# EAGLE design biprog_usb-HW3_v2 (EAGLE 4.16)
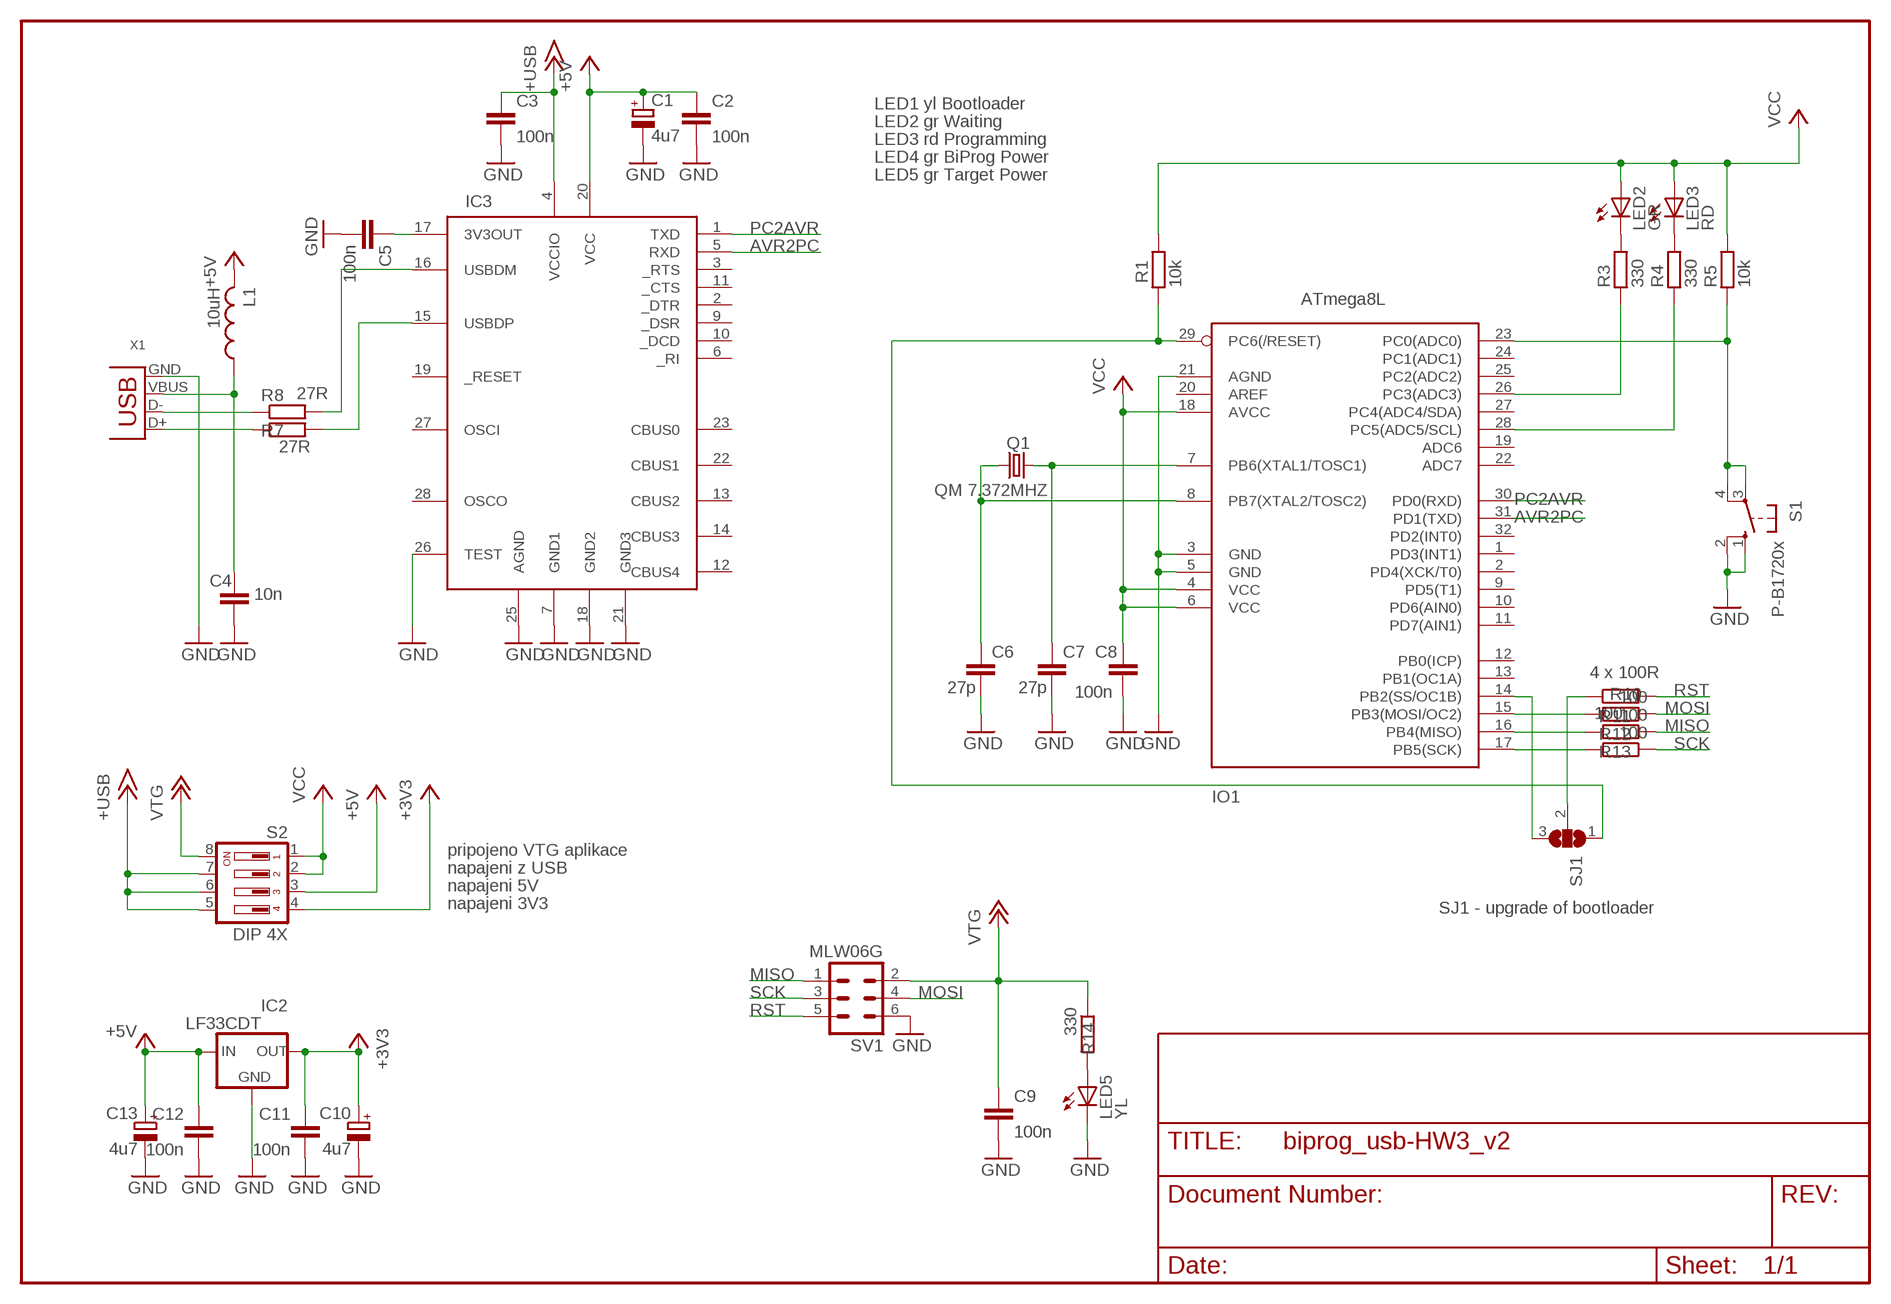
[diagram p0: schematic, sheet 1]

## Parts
C1  4u7  CPOL-EUSMCA  [SMC_A]
C2  100n  C-EUC1206  [C1206]
C3  100n  C-EUC1206  [C1206]
C4  10n  C-EUC1206  [C1206]
C5  100n  C-EUC1206  [C1206]
C6  27p  C-EUC1206  [C1206]
C7  27p  C-EUC1206  [C1206]
C8  100n  C-EUC1206  [C1206]
C9  100n  C-EUC1206  [C1206]
C10  4u7  CPOL-EUSMCA  [SMC_A]
C11  100n  C-EUC1206  [C1206]
C12  100n  C-EUC1206  [C1206]
C13  4u7  CPOL-EUSMCA  [SMC_A]
IC2  LF33CDT  LP2950CDTX-3.3  [DPACK]
IC3  FT232RL  [SSOP28DB]
IO1  ATmega8L  MEGA8-AI  [TQFP32-08]
L1  10uH  L-US0207/10  [0207/10]
LED2  GR  LED3MM  [LED3MM]
LED3  RD  LED3MM  [LED3MM]
LED5  YL  LED3MM  [LED3MM]
Q1  QM 7.372MHZ  CRYTALHC49S  [HC49/S]
R1  10k  R-EU_R1206  [R1206]
R3  330  R-EU_R1206  [R1206]
R4  330  R-EU_R1206  [R1206]
R5  10k  R-EU_R1206  [R1206]
R7  27R  R-EU_R1206  [R1206]
R8  27R  R-EU_R1206  [R1206]
R10  100  R-EU_R1206  [R1206]
R11  100  R-EU_R1206  [R1206]
R12  100  R-EU_R1206  [R1206]
R13  100  R-EU_R1206  [R1206]
R14  330  R-EU_R1206  [R1206]
S1  P-B1720x  10-XX  [B3F-10XX]
S2  DIP 4X  DS04  [DS-04]
SJ1  SJ2W  [SJ_2]
SV1  MLW06G  ML6  [ML6]
X1  USB-MINI B F SMD  USB-MB-S  [USB-MB-S]

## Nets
+3V3: C10.+ C11.1 IC2.3(OUT) S2.4
+5V: C1.+ C2.1 C12.1 C13.+ IC2.1(IN) IC3.20(VCC) L1.2 S2.3
+12V: C9.1 R14.1 S2.8 SV1.2 ; supply symbol labelled VTG
+15V: C3.1 IC3.4(VCCIO) S2.5 S2.6 S2.7 ; supply symbol labelled +USB
AVR2PC: IC3.5(RXD) IO1.31(PD1(TXD))
GND: C1.- C2.2 C3.2 C4.2 C5.2 C6.2 C7.2 C8.1 C9.2 C10.- C11.2 C12.2 C13.- IC2.4(GND) IC3.7(GND1) IC3.18(GND2) IC3.21(GND3) IC3.25(AGND) IC3.26(TEST) IO1.3(GND) IO1.5(GND) IO1.21(AGND) LED5.K(C) S1.1(S) S1.2(S1) SV1.6 X1.GND
MISO: R12.1 SV1.1
MOSI: R11.1 SV1.4
N$1: C7.1 IO1.7(PB6(XTAL1/TOSC1)) Q1.1
N$2: LED2.K(C) R3.2
N$3: LED3.K(C) R4.2
N$4: IO1.23(PC0(ADC0)) R5.1 S1.3(P) S1.4(P1)
N$6: LED5.A R14.2
N$8: C4.1 L1.1 X1.VBUS
N$9: IC3.15(USBDP) R8.2
N$11: C6.1 IO1.8(PB7(XTAL2/TOSC2)) Q1.2
N$12: R7.1 X1.D-
N$13: R8.1 X1.D+
N$16: IO1.17(PB5(SCK)) R13.2
N$17: IO1.16(PB4(MISO)) R12.2
N$18: IO1.15(PB3(MOSI/OC2)) R11.2
N$19: R10.1 SJ1.2
N$20: IO1.14(PB2(SS/OC1B)) SJ1.3
N$22: IC3.16(USBDM) R7.2
N$23: C5.1 IC3.17(3V3OUT)
N$24: IO1.29(PC6(/RESET)) R1.1 SJ1.1
N$37: IO1.26(PC3(ADC3)) R3.1
N$40: IO1.28(PC5(ADC5/SCL)) R4.1
PC2AVR: IC3.1(TXD) IO1.30(PD0(RXD))
RST: R10.2 SV1.5
SCK: R13.1 SV1.3
VCC: C8.2 IO1.4(VCC) IO1.6(VCC) IO1.18(AVCC) LED2.A LED3.A R1.2 R5.2 S2.1 S2.2
Unconnected: IC3.2(_DTR) IC3.3(_RTS) IC3.6(_RI) IC3.9(_DSR) IC3.10(_DCD) IC3.11(_CTS) IC3.12(CBUS4) IC3.13(CBUS2) IC3.14(CBUS3) IC3.19(_RESET) IC3.22(CBUS1) IC3.23(CBUS0) IC3.27(OSCI) IC3.28(OSCO) IO1.1(PD3(INT1)) IO1.2(PD4(XCK/T0)) IO1.9(PD5(T1)) IO1.10(PD6(AIN0)) IO1.11(PD7(AIN1)) IO1.12(PB0(ICP)) IO1.13(PB1(OC1A)) IO1.19(ADC6) IO1.20(AREF) IO1.22(ADC7) IO1.24(PC1(ADC1)) IO1.25(PC2(ADC2)) IO1.27(PC4(ADC4/SDA)) IO1.32(PD2(INT0))

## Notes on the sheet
- LED1 yl Bootloader
- LED2 gr Waiting
- LED3 rd Programming
- LED4 gr BiProg Power
- LED5 gr Target Power
- 4 x 100R
- pripojeno VTG aplikace
- napajeni z USB
- napajeni 5V
- napajeni 3V3 | SJ1 - upgrade of bootloader

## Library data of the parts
C1 C10 C13 = rcl:CPOL-EU: POLARIZED CAPACITOR, European symbol
C2-C9 C11 C12 = rcl:C-EU: CAPACITOR, European symbol
IC2 = v-reg:LP2950?*: Source: http://cache.national.com/ds/LP/LP2950.pdf
IC3 = ftdichip:FT232RL: USB UART 4th Generation USB UART (USB <-> Serial) Controller
IO1 = avr:MEGA8: MICROCONTROLLER 8 Kbytes FLASH 1 kbytes SRAM 512 bytes EEPROM USART 6-channel 10 bit ADC 2-channel 8 bit ADC
L1 = rcl:L-US: INDUCTOR, American symbol
LED2 LED3 LED5 = led:LED: LED
Q1 = crystal:CRYTAL: CRYSTAL
R1 R3-R5 R7 R8 R10-R14 = rcl:R-EU_: RESISTOR, European symbol
S1 = switch-omron:10-XX: OMRON SWITCH
S2 = switch-dil:DS04: DIL/CODE SWITCH
SJ1 = jumper:SJ2W: SMD solder JUMPER
SV1 = con-harting-ml:ML6: HARTING
X1 = con-usb-3:USB: USB Connectors

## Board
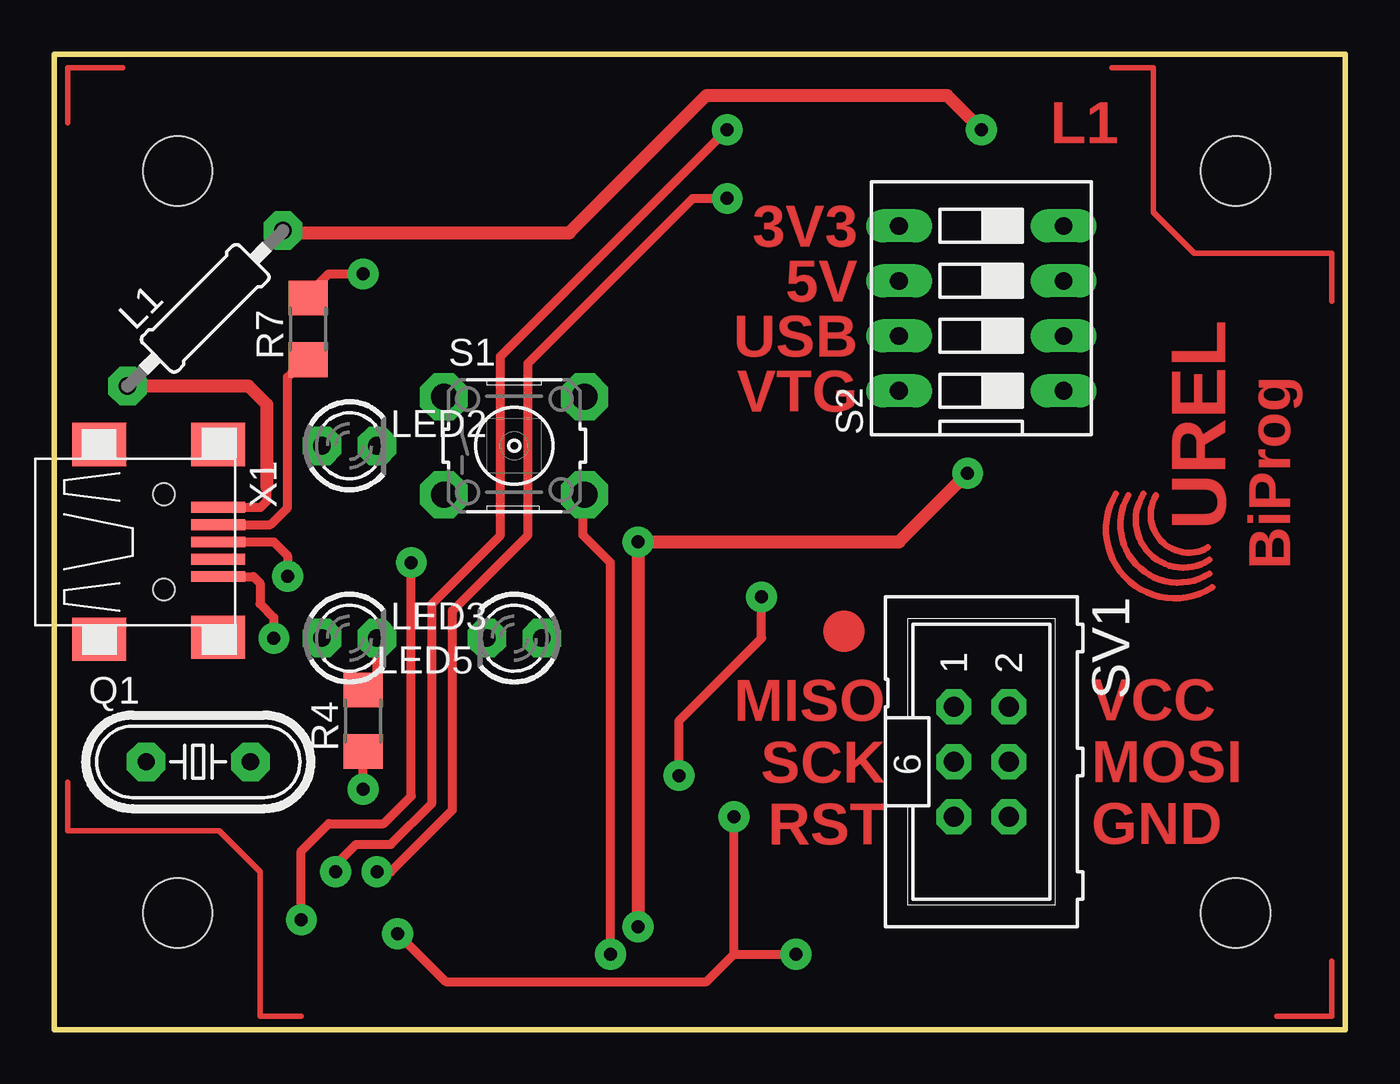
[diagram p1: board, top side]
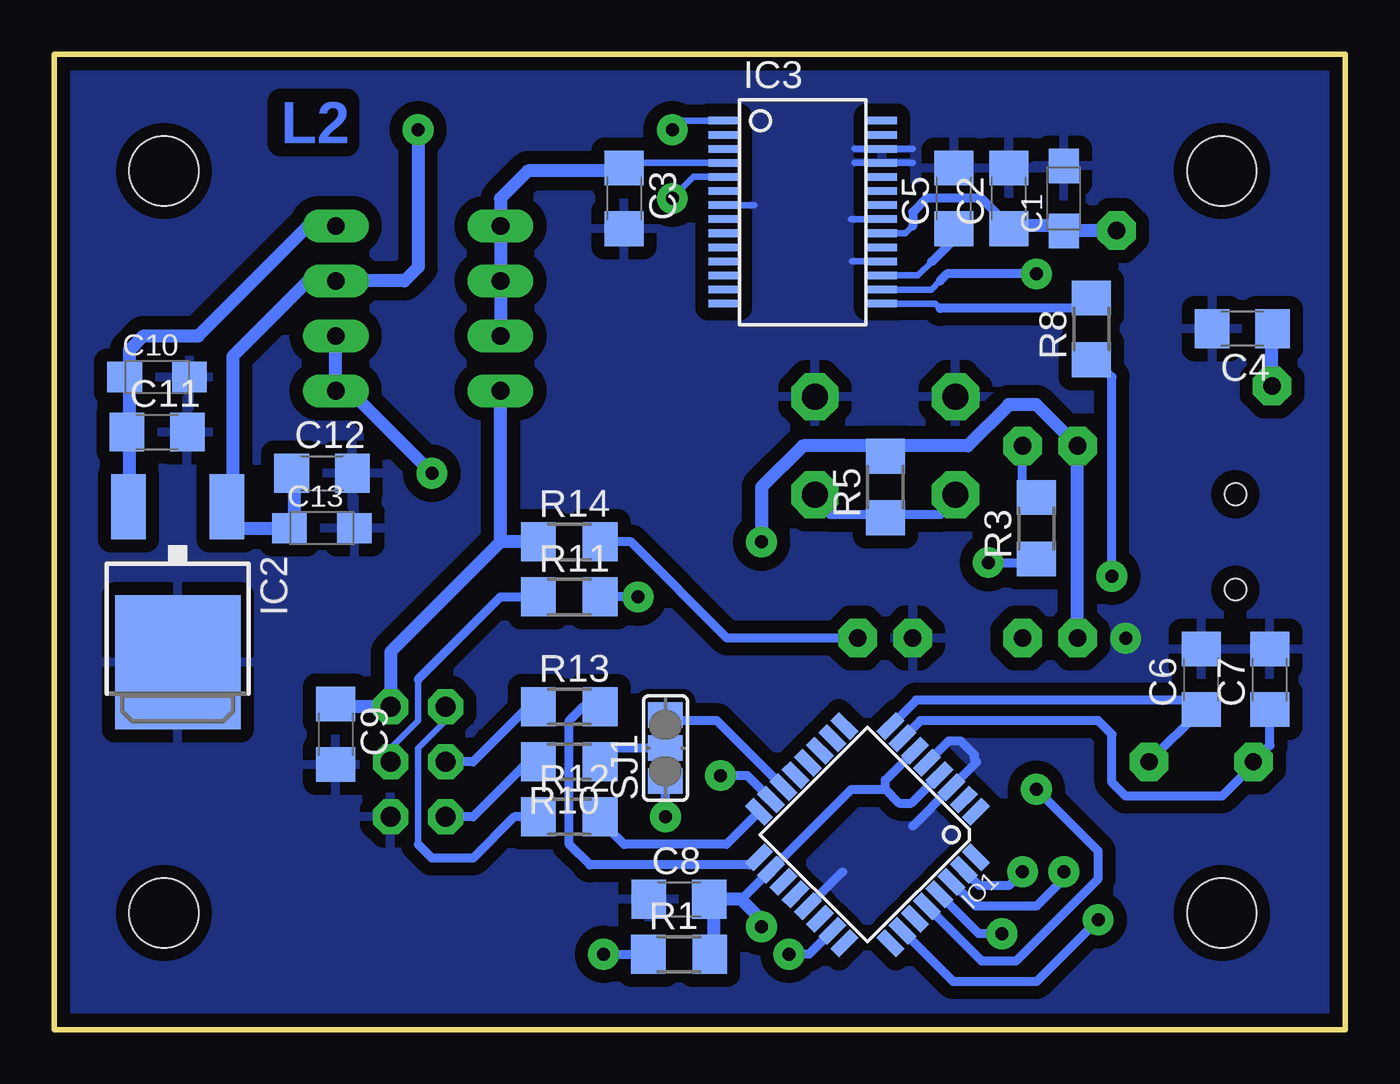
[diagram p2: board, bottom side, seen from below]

Size 59.69 x 45.09 mm. Coordinates in mm from the lower left corner, seen from the top.
Outline: 0,45.09 0,0 59.69,0 59.69,45.09 0,45.09
Copper layers (1*16): Top 0.035mm / dielectric 1.5mm / Bottom 0.035mm
Design rules "default": minimum track width 10mil, minimum drill 0.6mm, track to track 8mil, track to pad 8mil, pad to pad 8mil, via to via 8mil, smd to smd 8mil, copper to edge 1mil, drill to drill 8mil, minimum pad ring 14mil, minimum via ring 8mil, stop-mask expansion 4mil, vias tented up to drill 0.6mm, thermal gap 24mil
Holes 3.2 mm at 5.71,39.69 54.61,5.4 5.71,5.4 54.61,39.69

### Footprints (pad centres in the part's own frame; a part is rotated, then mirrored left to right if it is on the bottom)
SMC_A = smd 1.6 x 1.4: + -1.5,0; - 1.5,0
C1206 = smd 1.6 x 1.8: 1 -1.4,0; 2 1.4,0
DPACK = smd 1.6 x 3: 1 -2.28,-4.8; 3 2.28,-4.8 | smd 5.8 x 6.2: 4 0,2.38
SSOP28DB = smd 0.348 x 1.397: 1 -4.225,-3.656; 2 -3.575,-3.656; 3 -2.925,-3.656; 4 -2.275,-3.656; 5 -1.625,-3.656; 6 -0.975,-3.656; 7 -0.325,-3.656; 8 0.325,-3.656; 9 0.975,-3.656; 10 1.625,-3.656; 11 2.275,-3.656; 12 2.925,-3.656; 13 3.575,-3.656; 14 4.225,-3.656; 15 4.225,3.656; 16 3.575,3.656; 17 2.925,3.656; 18 2.275,3.656; 19 1.625,3.656; 20 0.975,3.656; 21 0.325,3.656; 22 -0.325,3.656; 23 -0.975,3.656; 24 -1.625,3.656; 25 -2.275,3.656; 26 -2.925,3.656; 27 -3.575,3.656; 28 -4.225,3.656
TQFP32-08 = smd 1.27 x 0.559: 1 -4.293,2.8; 2 -4.293,2; 3 -4.293,1.2; 4 -4.293,0.4; 5 -4.293,-0.4; 6 -4.293,-1.2; 7 -4.293,-2; 8 -4.293,-2.8; 17 4.293,-2.8; 18 4.293,-2; 19 4.293,-1.2; 20 4.293,-0.4; 21 4.293,0.4; 22 4.293,1.2; 23 4.293,2; 24 4.293,2.8 | smd 0.559 x 1.27: 9 -2.8,-4.293; 10 -2,-4.293; 11 -1.2,-4.293; 12 -0.4,-4.293; 13 0.4,-4.293; 14 1.2,-4.293; 15 2,-4.293; 16 2.8,-4.293; 25 2.8,4.293; 26 2,4.293; 27 1.2,4.293; 28 0.4,4.293; 29 -0.4,4.293; 30 -1.2,4.293; 31 -2,4.293; 32 -2.8,4.293
0207/10 = drill 0.813 pad 1.778 octagon: 1 -5.08,0; 2 5.08,0
LED3MM = drill 0.813 pad 1.778 octagon: A -1.27,0; K 1.27,0
HC49/S = drill 0.8 pad 1.778 octagon: 1 -2.413,0; 2 2.413,0
R1206 = smd 1.6 x 1.803: 1 -1.422,0; 2 1.422,0
B3F-10XX = drill 1.2 pad 2.184 octagon: 1 -3.251,2.261; 2 3.251,2.261; 3 -3.251,-2.261; 4 3.251,-2.261
DS-04 = drill 0.813 long: 1 -3.81,-3.81; 2 -1.27,-3.81; 3 1.27,-3.81; 4 3.81,-3.81; 5 3.81,3.81; 6 1.27,3.81; 7 -1.27,3.81; 8 -3.81,3.81
SJ_2 = smd 1.168 x 1.6: 1 -1.524,0; 2 0,0; 3 1.524,0
ML6 = drill 0.914 octagon: 1 -2.54,-1.27; 2 -2.54,1.27; 3 0,-1.27; 4 0,1.27; 5 2.54,-1.27; 6 2.54,1.27
USB-MB-S = smd 2.5 x 0.5: D+ 2.5,0; D- 2.5,0.8; GND 2.5,-1.6; ID 2.5,-0.8; VBUS 2.5,1.6 | smd 2.5 x 2: P$1 -3,-4.5; P$2 -3,4.5; P$3 2.5,-4.4; P$4 2.5,4.5 | hole 1: 0,2.2; 0,-2.2

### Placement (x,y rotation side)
C1  13.02,38.42 90 bottom
C2  15.56,38.42 90 bottom
C3  33.34,38.42 270 bottom
C4  4.76,32.38 180 bottom
C5  18.1,38.42 90 bottom
C6  6.67,16.19 90 bottom
C7  3.49,16.19 90 bottom
C8  30.8,6.03 0 bottom
C9  46.67,13.65 270 bottom
C10  54.93,30.16 0 bottom
C11  54.93,27.62 0 bottom
C12  47.31,25.72 0 bottom
C13  47.31,23.18 0 bottom
IC2  53.98,19.37 180 bottom
IC3  25.08,37.78 270 bottom
IO1  22.09,9.02 225 bottom
L1  6.99,33.34 45 top
LED2  13.65,26.99 0 top
LED3  13.65,18.1 0 top
LED5  21.27,18.1 180 top
Q1  6.67,12.38 0 top
R1  30.8,3.49 0 bottom
R3  14.29,23.18 90 bottom
R4  14.29,14.29 90 top
R5  21.27,25.08 90 bottom
R7  11.75,32.38 90 top
R8  11.75,32.38 90 bottom
R10  35.88,12.38 180 bottom
R11  35.88,20 0 bottom
R12  35.88,9.84 0 bottom
R13  35.88,14.92 0 bottom
R14  35.88,22.54 0 bottom
S1  21.27,26.99 0 top
S2  42.86,33.34 90 top
SJ1  31.43,13.02 90 bottom
SV1  42.86,12.38 270 top
X1  5.08,22.54 0 top

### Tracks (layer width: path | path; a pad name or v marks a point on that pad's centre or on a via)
+3V3
  Bottom 0.406: IC2.3 56.26,23.87 56.2,24.45 | 56.2,27.62 C11.1 | 56.2,30.16 C10.+
  Bottom 0.61: 56.2,24.45 56.2,27.62 56.2,30.16 56.2,31.43 55.56,32.07 53.02,32.07 47.94,37.15 S2.4
+5V  (via drill 0.6 pad 1.42)
  Top 0.406: L1.2 10.48,36.83
  Top 0.61: 10.48,36.83 23.81,36.83 30.16,43.18 41.27,43.18 v42.86,41.59
  Bottom 0.305: IC3.20 20.34,36.81 20,37.15
  Bottom 0.406: 20,37.15 20,37.78 19.37,38.42 16.83,38.42 15.56,37.15 C2.1 | 12.8,36.93 13.02,37.15 | 51.44,24.77 51.7,24.39 IC2.1 | 48.58,25.72 C12.1 | 51.7,23.23 51.75,23.18 | 48.58,23.18 C13.+
  Bottom 0.61: C1.+ 13.02,37.15 15.56,37.15 | L1.2 12.8,36.93 | v42.86,41.59 42.86,35.24 43.5,34.61 S2.3 47.94,34.61 51.44,31.11 51.44,24.77 | 48.58,25.72 48.58,23.18 51.75,23.18 | IC2.1 51.7,23.23
+12V
  Bottom 0.406: 46.67,14.92 C9.1 | R14.1 37.15,22.54
  Bottom 0.61: 46.67,14.92 SV1.2 44.13,17.46 39.05,22.54 | 39.05,22.54 S2.8 | R14.1 39.05,22.54
+15V
  Bottom 0.305: IC3.4 32.97,40.06 33.34,39.69
  Bottom 0.406: 33.34,39.69 C3.1
  Bottom 0.61: S2.7 S2.6 S2.5 39.05,38.42 37.78,39.69 33.34,39.69
AVR2PC  (via drill 0.6 pad 1.42)
  Top 0.406: v31.11,38.42 29.53,38.42 21.91,30.8 21.91,22.86 18.41,19.37 18.41,10.16 15.56,7.3 v14.92,7.3
  Bottom 0.305: IC3.5 30.12,39.41 v31.11,38.42
  Bottom 0.406: IO1.31 16.91,6.67 15.56,6.67 v14.92,7.3
GND  (via drill 0.6 pad 1.42)
  Top 0.406: X1.GND 9.22,20.94 9.53,20.64 9.53,19.68 10.16,19.05 v10.16,18.1
  Bottom 0.305: 21.27,40.71 IC3.26 | 20,40.71 21.27,40.71 | 21.27,40.06 IC3.25 | 20,40.06 21.27,40.06 | 21.27,40.71 22.7,40.71 | 21.27,40.06 22.7,40.06 | IC3.21 22.86,37.46 | 21.27,35.51 IC3.18 22.81,35.51 | 27.3,38.11 IC3.7
  Bottom 0.406: IO1.21 23.25,7.3 | 20,9.41 IO1.3 17.04,12.38 17.14,12.49 17.14,12.7 17.78,13.34 18.35,13.34 IO1.5
  pour Bottom (isolate 0.61): -0.32,45.4 -0.32,-0.32 60.01,-0.32 60.01,45.4
MISO
  Bottom 0.305: 42.86,8.57 42.86,13.02 41.59,14.29 SV1.1
  Bottom 0.406: R12.1 38.42,9.84 40.32,7.94 42.23,7.94 42.86,8.57
MOSI
  Bottom 0.305: SV1.4 44.13,13.02 42.86,14.29 42.86,16.19
  Bottom 0.406: 42.86,16.19 39.05,20 R11.1 37.15,20
N$1
  Bottom 0.406: 3.49,14.92 C7.1 3.49,13.14 Q1.1 4.25,12.26 5.71,10.79 10.16,10.79 10.79,11.43 10.79,13.65 11.43,14.29 19.66,14.29 IO1.7
N$2
  Bottom 0.406: R3.2 14.29,24.45 14.92,25.08 LED2.K
N$3
  Top 0.406: R4.2 14.77,15.71 14.92,15.56 LED3.K
N$4  (via drill 0.6 pad 1.42)
  Top 0.406: v25.72,3.49 25.72,21.59 24.45,22.86 24.45,24.45 24.52,24.52 S1.4
  Bottom 0.406: IO1.23 24.79,3.49 v25.72,3.49 | S1.3 18.02,24.52 18.73,23.81 21.27,23.81 | S1.4 24.52,24.52 23.81,23.81 21.27,23.81 | 21.27,23.81 R5.1
N$6
  Bottom 0.406: LED5.A 28.57,18.1 33.02,22.54 R14.2 34.61,22.54
N$8
  Top 0.406: X1.VBUS 9.54,24.14 9.84,24.45 9.84,25.08
  Top 0.61: 9.84,25.08 9.84,28.89 8.99,29.75 L1.1
  Bottom 0.406: C4.1 3.49,32.38 3.39,32.28
  Bottom 0.61: L1.1 3.39,32.28
N$9
  Bottom 0.305: IC3.15 18.95,33.56 18.73,33.34
  Bottom 0.406: R8.2 11.75,33.34 18.73,33.34
N$10
  Top 0.254: 0.64,41.91 0.64,44.45 3.17,44.45
N$11
  Bottom 0.406: C6.1 6.67,15.24 19.84,15.24 IO1.8 | C6.1 Q1.2 | C6.1 6.67,14.92
N$12
  Top 0.406: X1.D- 10.01,23.34 10.79,24.13 10.79,30.16 11.75,31.11 R7.1
N$13  (via drill 0.6 pad 1.42)
  Top 0.406: X1.D+ 10.16,22.54 10.79,21.91 v10.79,20.95
  Bottom 0.406: R8.1 11.6,30.96 10.79,30.16 v10.79,20.95
N$16
  Bottom 0.406: R13.2 35.24,14.92 35.88,14.29 35.88,8.57 34.92,7.62 27.55,7.62 27.11,8.06 IO1.17
N$17
  Bottom 0.406: IO1.16 28.61,8.57 33.34,8.57 34.61,9.84 R12.2
N$18  (via drill 0.6 pad 1.42)
  Top 0.406: v32.7,20 32.7,18.1 28.89,14.29 v28.89,11.75
  Bottom 0.406: v32.7,20 R11.2 | IO1.15 27.65,11.75 v28.89,11.75
N$19
  Bottom 0.406: R10.1 34.61,12.38 33.97,13.02 SJ1.2
N$20
  Bottom 0.406: SJ1.3 30.8,14.29 29.06,14.29 IO1.14
N$22  (via drill 0.6 pad 1.42)
  Top 0.406: R7.2 11.75,33.97 12.7,34.92 v14.29,34.92
  Bottom 0.305: IC3.16 19.13,34.21 18.73,34.61
  Bottom 0.406: v14.29,34.92 18.41,34.92 18.73,34.61
N$23
  Bottom 0.305: IC3.17 19.75,34.86 19.12,35.49
  Bottom 0.406: C5.1 18.1,36.51 19.12,35.49
N$24  (via drill 0.6 pad 1.42)
  Top 0.406: v15.88,4.45 18.1,2.22 30.16,2.22 31.43,3.49 | 31.43,3.49 v31.43,9.84 | 31.43,3.49 v34.29,3.49
  Bottom 0.406: v31.43,9.84 SJ1.1 | IO1.29 16.95,4.45 v15.88,4.45 | v34.29,3.49 R1.1
N$26
  Top 0.254: 56.52,0.64 59.05,0.64 59.05,3.17
N$27
  Top 0.305: 50.93,24.7 arc151 53.34,22.29
N$28
  Top 0.305: 50.35,24.77 arc156 53.4,21.72
N$29
  Top 0.305: 49.66,24.7 arc153 53.4,21.08
N$30
  Top 0.305: 49.09,24.77 arc154 53.53,20.45
N$31
  Top 0.254: 48.9,44.45 50.8,44.45 50.8,37.78 52.7,35.88 59.05,35.88 59.05,33.66
N$32
  Top 0.254: 0.64,11.43 0.64,9.21 7.62,9.21 9.53,7.3 9.53,0.64 11.43,0.64
N$37  (via drill 0.6 pad 1.42)
  Top 0.406: v11.43,5.08 11.43,8.26 12.7,9.53 15.24,9.53 16.51,10.79 v16.51,21.59
  Bottom 0.406: IO1.26 18.12,2.22 14.29,2.22 v11.43,5.08 | R3.1 14.14,21.76 13.97,21.59 v16.51,21.59
N$40  (via drill 0.6 pad 1.42)
  Top 0.406: v14.29,11.11 R4.1
  Bottom 0.406: IO1.28 16.81,3.17 15.24,3.17 11.43,6.99 11.43,8.26 v14.29,11.11
PC2AVR  (via drill 0.6 pad 1.42)
  Top 0.406: v31.11,41.59 20.64,31.11 20.64,22.86 17.46,19.68 17.46,10.48 15.56,8.57 13.97,8.57 13.02,7.62 v13.02,7.3
  Bottom 0.305: IC3.1 30.7,42.01 v31.11,41.59
  Bottom 0.406: IO1.30 17.09,5.71 14.29,5.71 13.02,6.99 v13.02,7.3
RST
  Bottom 0.406: R10.2 37.78,12.38 40.32,9.84 SV1.5
SCK
  Bottom 0.406: R13.1 37.78,14.92 40.32,12.38 SV1.3
VCC  (via drill 0.6 pad 1.42)
  Top 0.61: v42.23,25.72 39.05,22.54 v26.99,22.54 v26.99,4.76
  Bottom 0.406: IO1.4 20.07,10.48 20.64,10.48 21.27,11.11 | 21.27,11.11 22.83,11.11 IO1.18 27.91,6.03 27.94,6.03 | IO1.6 21.27,11.54 21.27,11.11 | 29.53,6.03 C8.2 29.21,5.84 | 29.21,3.66 R1.2
  Bottom 0.61: C8.2 27.94,6.03 26.99,5.08 v26.99,4.76 | LED3.A LED2.A 14.29,28.89 15.56,28.89 17.46,26.99 21.27,26.99 | 21.27,26.99 25.08,26.99 26.99,25.08 v26.99,22.54 | 21.27,26.99 R5.2 | S2.2 S2.1 46.04,29.53 v42.23,25.72 | 29.21,5.84 29.21,3.66
(copper drawn outside any net)
  shapes: Top circle x1

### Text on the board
Top: L1 | 3V3 | 5V | USB | VTG | UREL | BiProg | MISO | VCC | SCK | MOSI | RST | GND
Bottom: L2
bValues: JP1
